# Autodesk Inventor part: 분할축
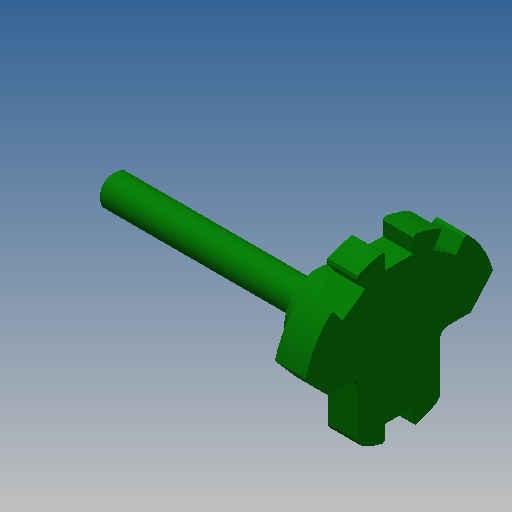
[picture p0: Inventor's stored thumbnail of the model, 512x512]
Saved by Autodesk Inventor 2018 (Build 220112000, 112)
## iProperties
Created: 2016-11
Part Number: 분할축
Material: 강철, 연강
Document SubType Name: Modeling
Designer: mduedu
Density: 1 g/cm^3
Appearance: 진녹색
Author: mduedu
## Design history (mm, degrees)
sketch "스케치1"
  geometry: C1 r 38 at (0, 0); 1 further point
  constraints: 1 centre point, 1 coincident
  dimensions: "d0" = 76 diameter of C1
extrude "돌출1" new body sketch "스케치1" distance "d1" = 12; taper "d2" = 0 deg
sketch "스케치2"
  geometry: L1 (0, 38)-(0, -38); L2 (5.5, 37.6)-(5.5, 31); L3 (5.5, 31)-(-5.5, 31); L4 (-5.5, 31)-(-5.5, 37.6); A1 r 38 centre (0, 0) between (0, 38) and (0, -38) reference; A2 r 38 centre (0, 0) between (5.5, 37.6) and (-5.5, 37.6); 2 further points
  constraints: 8 end point, 6 point on circle, 2 coincident, 2 vertical, 1 centre point, 1 horizontal, 1 midpoint, 1 parallel, 1 symmetric about line
  dimensions: "d3" = 11 distance of L2.end L3.end; "d5" = 31 distance from line of L3 point (0, 0)
extrude "돌출2" cut sketch "스케치2" extent not by distance; stored distance "d7" = 12; taper "d8" = 0 deg
sketch "스케치3"
  geometry: L1 (-16, 0)-(-38, 0); L2 (16, 0)-(38, 0); L3 (0, -28)-(0, 28); L4 (-16, -22.978)-(-16, 0); L5 (16, -22.978)-(16, 0); A1 r 38 centre (0, 0) between (-5.5, 37.6) and (-17.061, 33.955) reference; A2 r 38 centre (0, 0) between (-38, 0) and (38, 0); A3 r 28 centre (0, 0) between (-16, -22.978) and (16, -22.978); 4 further points
  constraints: 10 end point, 7 point on circle, 3 coincident, 2 centre point, 2 horizontal alignment, 2 midpoint, 2 parallel, 1 collinear, 1 horizontal, 1 perpendicular, 1 other
  dimensions: "d13" = 32 distance between parallel lines of L5 L4; "d14" = 28 radius of A3
extrude "돌출3" cut sketch "스케치3" extent not by distance; stored distance "d15" = 12; taper "d16" = 0 deg
sketch "스케치4"
  geometry: L1 (0, 0)-(0, -28); L2 (5.5, -27.455)-(5.5, -21); L3 (5.5, -21)-(-5.5, -21); L4 (-5.5, -21)-(-5.5, -27.455); A1 r 28 centre (0, 0) between (-16, -22.978) and (16, -22.978) reference; A2 r 28 centre (0, 0) between (16, -22.978) and (0, -28); A3 r 28 centre (0, 0) between (-5.5, -27.455) and (5.5, -27.455); 1 further point
  constraints: 8 end point, 7 point on circle, 2 centre point, 2 coincident, 1 horizontal, 1 parallel, 1 other
  dimensions: "d17" = 11 distance between parallel lines of L2 L4; "d19" = 21 distance from line of L3 point (0, 0)
extrude "돌출4" cut sketch "스케치4" extent not by distance; stored distance "d20" = 12; taper "d21" = 0 deg
sketch "스케치5"
  geometry: C1 r 13 at (0, 0); 1 further point
  constraints: 1 centre point, 1 coincident
  dimensions: "d22" = 26 diameter of C1
extrude "돌출5" join sketch "스케치5" distance "d23" = 20; taper "d24" = 0 deg
sketch "스케치6"
  geometry: C1 r 6 at (0, 0); 1 further point
  constraints: 1 centre point, 1 coincident
  dimensions: "d25" = 12 diameter of C1
extrude "돌출6" join sketch "스케치6" distance "d26" = 80; taper "d27" = 0 deg
fillet "모깎기1" dims "d28" = 3
chamfer "모따기1" distance "d29" = 1; stored, may be unused: second distance "d30" = 2, angle "d31" = 45 deg
sketch "스케치7"
  geometry: L1 (-20, 13)-(-20, -13) reference; L2 (-20, 6)-(-99, 6) reference; L3 (0, 0)-(-20, 0); C1 r 1 at (-21, 6)
  constraints: 2 end point, 1 centre point, 1 midpoint, 1 tangent
  dimensions: "d32" = 2 diameter of C1; "d33" = 10 dimension on C1 L3
revolve "회전1" sketch "스케치7" stored, may be unused: angle "d34" = 90 deg
chamfer "모따기2" distance "d35" = 1; stored, may be unused: second distance "d36" = 2, angle "d37" = 45 deg
chamfer "모따기3" distance "d38" = 10; stored, may be unused: second distance "d39" = 2, angle "d40" = 45 deg
chamfer "모따기4" distance "d41" = 1; stored, may be unused: second distance "d42" = 2, angle "d43" = 45 deg
fillet "모깎기2" dims "d44" = 3
node "솔리드1"
pattern_circular "원형 패턴1" dims angle "d10" = 35 deg
other parameters: "d12" = 56
